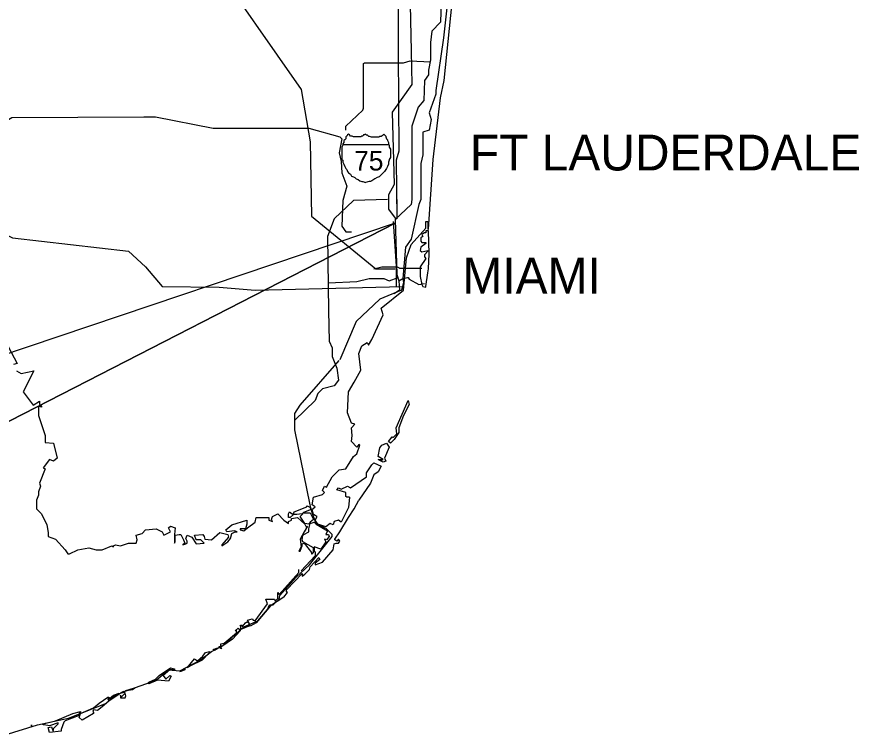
# Model space of a CAD drawing. Extents: x -820.2 to -798.1, y -2199.1 to -2182.2.
# Drawn here: x -805.629 to -804.571, y -2186.377 to -2185.475 of the extents above; entities that cross this region are included whole.
import ezdxf

# ---------------------------------------------------------------- set-up
doc = ezdxf.new("R2010")
doc.units = 0
for name, color, linetype in [('FLMap1', 7, 'Continuous'), ('FLMap2', 7, 'Continuous'), ('FLMap3', 7, 'Continuous'), ('TextMisc', 7, 'Continuous'), ('TextProjLabel', 7, 'Continuous')]:
    doc.layers.add(name, color=color, linetype=linetype)

msp = doc.modelspace()

# ---------------------------------------------------------------- linework, layer by layer
at = {"layer": 'FLMap1'}
msp.add_line((-805.2192, -2185.6357), (-805.1607, -2185.6357), dxfattribs=at)
for points in [[(-805.1904, -2185.6228), (-805.1919, -2185.6237), (-805.1929, -2185.6237), (-805.1939, -2185.6252), (-805.1954, -2185.6252), (-805.1964, -2185.6262), (-805.1979, -2185.6262), (-805.1989, -2185.6262), (-805.1999, -2185.6262), (-805.2013, -2185.6262), (-805.2038, -2185.6262), (-805.2048, -2185.6262), (-805.2058, -2185.6262), (-805.2073, -2185.6252), (-805.2093, -2185.6252), (-805.2108, -2185.6237), (-805.2118, -2185.6228), (-805.2132, -2185.6237), (-805.2142, -2185.6252), (-805.2152, -2185.6262), (-805.2152, -2185.6287), (-805.2167, -2185.6297), (-805.2177, -2185.6307), (-805.2177, -2185.6332), (-805.2192, -2185.6347), (-805.2192, -2185.6366), (-805.2202, -2185.6391), (-805.2202, -2185.6416), (-805.2202, -2185.6451), (-805.2202, -2185.6476), (-805.2202, -2185.65), (-805.2202, -2185.652), (-805.2202, -2185.6545), (-805.2192, -2185.6555), (-805.2192, -2185.658), (-805.2177, -2185.6605), (-805.2167, -2185.6634), (-805.2152, -2185.6659), (-805.2142, -2185.6669), (-805.2132, -2185.6694), (-805.2118, -2185.6714), (-805.2093, -2185.6729), (-805.2083, -2185.6753), (-805.2058, -2185.6763), (-805.2038, -2185.6773), (-805.2023, -2185.6788), (-805.1999, -2185.6798), (-805.1979, -2185.6813), (-805.1954, -2185.6823), (-805.1939, -2185.6823), (-805.1904, -2185.6833)], [(-805.1904, -2185.6228), (-805.1894, -2185.6237), (-805.1884, -2185.6237), (-805.187, -2185.6252), (-805.186, -2185.6252), (-805.1835, -2185.6262), (-805.1825, -2185.6262), (-805.181, -2185.6262), (-805.18, -2185.6262), (-805.179, -2185.6262), (-805.1775, -2185.6262), (-805.1745, -2185.6262), (-805.1736, -2185.6262), (-805.1726, -2185.6252), (-805.1711, -2185.6252), (-805.1686, -2185.6237), (-805.1676, -2185.6228), (-805.1666, -2185.6237), (-805.1651, -2185.6252), (-805.1651, -2185.6262), (-805.1641, -2185.6287), (-805.1631, -2185.6297), (-805.1631, -2185.6307), (-805.1617, -2185.6332), (-805.1617, -2185.6347), (-805.1607, -2185.6366), (-805.1607, -2185.6391), (-805.1592, -2185.6416), (-805.1592, -2185.6451), (-805.1592, -2185.6476), (-805.1592, -2185.65), (-805.1592, -2185.652), (-805.1607, -2185.6545), (-805.1607, -2185.6555), (-805.1617, -2185.658), (-805.1617, -2185.6605), (-805.1631, -2185.6634), (-805.1641, -2185.6659), (-805.1651, -2185.6669), (-805.1666, -2185.6694), (-805.1686, -2185.6714), (-805.1701, -2185.6729), (-805.1726, -2185.6753), (-805.1736, -2185.6763), (-805.176, -2185.6773), (-805.179, -2185.6788), (-805.18, -2185.6798), (-805.1825, -2185.6813), (-805.1845, -2185.6823), (-805.186, -2185.6823), (-805.1904, -2185.6833)]]:
    msp.add_lwpolyline(points, dxfattribs=at)
at = {"layer": 'FLMap2'}
for points in [[(-805.6126, -2185.2521), (-805.5635, -2185.2531), (-805.5625, -2185.2556), (-805.5625, -2185.2928), (-805.4831, -2185.2938), (-805.4554, -2185.3082), (-805.44, -2185.3246), (-805.4236, -2185.3236), (-805.4077, -2185.3325), (-805.3958, -2185.3345), (-805.3899, -2185.3454), (-805.3889, -2185.398), (-805.2713, -2185.5667), (-805.2599, -2185.6322), (-805.2584, -2185.7255)], [(-805.0917, -2185.5553), (-805.0818, -2185.4575), (-805.0709, -2185.3851), (-805.0709, -2185.2978)], [(-805.1497, -2185.3335), (-805.1497, -2185.5201), (-805.1488, -2185.6441), (-805.1522, -2185.6555), (-805.1512, -2185.7289)], [(-805.0803, -2185.3955), (-805.0857, -2185.4372), (-805.0927, -2185.5017), (-805.1021, -2185.5677), (-805.1021, -2185.5726), (-805.1105, -2185.596), (-805.1081, -2185.6044), (-805.1105, -2185.6178), (-805.1185, -2185.6203), (-805.1185, -2185.6486), (-805.121, -2185.6595), (-805.121, -2185.7046), (-805.1234, -2185.7111), (-805.1334, -2185.7547), (-805.1403, -2185.7646), (-805.1438, -2185.8038), (-805.1428, -2185.8093), (-805.1453, -2185.8187), (-805.1726, -2185.8301), (-805.2023, -2185.8579), (-805.2227, -2185.906)], [(-805.9029, -2185.4575), (-805.8994, -2185.533), (-805.8979, -2185.5984), (-805.8949, -2185.6143), (-805.881, -2185.6237), (-805.8607, -2185.6486), (-805.7947, -2185.6952), (-805.7888, -2185.6967), (-805.7808, -2185.7036), (-805.763, -2185.7101), (-805.7515, -2185.7111), (-805.7446, -2185.718), (-805.7188, -2185.7289), (-805.6994, -2185.7324), (-805.6816, -2185.7393), (-805.6672, -2185.7408), (-805.6603, -2185.7393), (-805.634, -2185.7527), (-805.4881, -2185.7696)], [(-805.115, -2185.7324), (-805.1125, -2185.7324), (-805.1125, -2185.7418), (-805.1115, -2185.7418), (-805.1056, -2185.6545), (-805.0962, -2185.5771), (-805.0917, -2185.5553)], [(-805.1512, -2185.7046), (-805.1512, -2185.7289)], [(-805.2584, -2185.7255), (-805.1775, -2185.7919), (-805.1532, -2185.7919)], [(-805.2073, -2186.0013), (-805.2083, -2185.9914), (-805.2038, -2185.9869), (-805.2083, -2185.9854), (-805.2132, -2185.9725), (-805.2118, -2185.9462), (-805.2048, -2185.9343), (-805.1964, -2185.9189), (-805.1989, -2185.8981), (-805.1954, -2185.8887), (-805.1884, -2185.8842), (-805.187, -2185.8877), (-805.1825, -2185.8807), (-805.1686, -2185.8495), (-805.1711, -2185.841), (-805.1428, -2185.8187), (-805.1393, -2185.778), (-805.1334, -2185.7612), (-805.115, -2185.7408), (-805.115, -2185.7324)], [(-805.1557, -2185.7324), (-805.1522, -2185.7885), (-805.1522, -2185.8093)], [(-805.115, -2185.8148), (-805.115, -2185.8138), (-805.1125, -2185.7969), (-805.1115, -2185.7919), (-805.1105, -2185.7731), (-805.1115, -2185.7443), (-805.114, -2185.7443), (-805.115, -2185.7443), (-805.115, -2185.7468), (-805.115, -2185.7468), (-805.1165, -2185.7468), (-805.1185, -2185.7478), (-805.12, -2185.7488), (-805.1185, -2185.7513), (-805.121, -2185.7527), (-805.121, -2185.7572), (-805.12, -2185.7587), (-805.115, -2185.7587), (-805.115, -2185.7602), (-805.121, -2185.7646), (-805.122, -2185.7686), (-805.12, -2185.7706), (-805.1125, -2185.7686), (-805.1125, -2185.7696), (-805.1165, -2185.7741), (-805.1165, -2185.7766), (-805.115, -2185.779), (-805.122, -2185.7895), (-805.122, -2185.8014), (-805.12, -2185.8113), (-805.1185, -2185.8138), (-805.115, -2185.8148)], [(-805.4881, -2185.7696), (-805.4668, -2185.7895), (-805.4459, -2185.8138), (-805.3745, -2185.8148), (-805.3293, -2185.8187), (-805.1438, -2185.8138)], [(-805.1522, -2185.8093), (-805.1522, -2185.8138)], [(-805.1428, -2185.8038), (-805.1378, -2185.8028), (-805.1368, -2185.8028), (-805.1359, -2185.8048), (-805.1234, -2185.8113), (-805.1165, -2185.8103)], [(-805.6479, -2185.8733), (-805.628, -2185.9105), (-805.6325, -2185.912)], [(-805.6444, -2186.3774), (-805.6027, -2186.3645), (-805.5635, -2186.356), (-805.5159, -2186.3372), (-805.506, -2186.3282), (-805.4926, -2186.3223), (-805.4534, -2186.3084), (-805.438, -2186.2955), (-805.4236, -2186.2965), (-805.3983, -2186.2831), (-805.3839, -2186.2722), (-805.37, -2186.2652), (-805.3432, -2186.2414), (-805.3259, -2186.234), (-805.3135, -2186.2196), (-805.311, -2186.2136), (-805.3065, -2186.2136), (-805.2991, -2186.2067), (-805.2981, -2186.2022), (-805.2777, -2186.1789), (-805.2609, -2186.1635), (-805.2326, -2186.1278), (-805.2326, -2186.1253), (-805.2395, -2186.1184), (-805.249, -2186.1134), (-805.2524, -2186.1114), (-805.2574, -2186.098), (-805.2599, -2186.0881), (-805.2792, -2185.9939), (-805.2792, -2185.9735), (-805.2728, -2185.9631), (-805.2237, -2185.907)], [(-805.629, -2185.9199), (-805.623, -2185.9234), (-805.6072, -2185.9199), (-805.6206, -2185.9462), (-805.6082, -2185.9631), (-805.6002, -2185.9581), (-805.6002, -2185.9621), (-805.5977, -2185.9641), (-805.5977, -2185.9656), (-805.6012, -2185.9641), (-805.6012, -2185.976), (-805.5928, -2186.0013), (-805.5928, -2186.0097), (-805.5824, -2186.0107), (-805.5779, -2186.0296), (-805.5824, -2186.0335), (-805.5873, -2186.0311), (-805.5953, -2186.0415)], [(-805.1592, -2186.0107), (-805.1617, -2186.0087), (-805.1572, -2186.0028), (-805.1557, -2186.0038), (-805.1512, -2185.9988), (-805.1522, -2185.9914), (-805.1368, -2185.9571), (-805.1359, -2185.9621), (-805.1428, -2185.976), (-805.1488, -2185.9914), (-805.1488, -2185.9973), (-805.1547, -2186.0063), (-805.1592, -2186.0107), (-805.1617, -2186.0087)], [(-805.2559, -2186.0787), (-805.2445, -2186.0752), (-805.242, -2186.0727), (-805.2445, -2186.0703), (-805.242, -2186.0648), (-805.2395, -2186.0658), (-805.2326, -2186.0529), (-805.2237, -2186.044), (-805.2152, -2186.043), (-805.2058, -2186.0276), (-805.2013, -2186.0241), (-805.1979, -2186.0132), (-805.1989, -2186.0122), (-805.2013, -2186.0157), (-805.2083, -2186.0087), (-805.2073, -2186.0013)], [(-805.1701, -2186.0321), (-805.1686, -2186.0311), (-805.1745, -2186.0276), (-805.1726, -2186.0167), (-805.1701, -2186.0132), (-805.1641, -2186.0107), (-805.1607, -2186.0157), (-805.1666, -2186.0296), (-805.1651, -2186.0335), (-805.1686, -2186.0345), (-805.1711, -2186.0335), (-805.1745, -2186.0311), (-805.1745, -2186.0311), (-805.1711, -2186.0311), (-805.1701, -2186.0321), (-805.1686, -2186.0311)], [(-805.5953, -2186.0415), (-805.5928, -2186.043), (-805.6002, -2186.0608), (-805.5987, -2186.0648), (-805.6012, -2186.0717), (-805.6012, -2186.0762), (-805.6037, -2186.0822), (-805.6037, -2186.0931), (-805.5977, -2186.0995), (-805.5908, -2186.1134), (-805.5893, -2186.1228), (-805.5893, -2186.1278), (-805.5799, -2186.1313), (-805.568, -2186.1447), (-805.5645, -2186.1496), (-805.5625, -2186.1496), (-805.5521, -2186.1447), (-805.5382, -2186.1422), (-805.5288, -2186.1447), (-805.5213, -2186.1447), (-805.5094, -2186.1397), (-805.507, -2186.1407), (-805.507, -2186.1397), (-805.5045, -2186.1382), (-805.4985, -2186.1397), (-805.4881, -2186.1362), (-805.4787, -2186.1362), (-805.4772, -2186.1323), (-805.4787, -2186.1263), (-805.4712, -2186.1243), (-805.4668, -2186.1194), (-805.4534, -2186.1184), (-805.4459, -2186.1219), (-805.4439, -2186.1263), (-805.4355, -2186.1219), (-805.438, -2186.1169), (-805.4355, -2186.1149), (-805.4296, -2186.1169), (-805.4305, -2186.1253), (-805.4305, -2186.1323), (-805.4305, -2186.1362), (-805.4296, -2186.1348), (-805.4296, -2186.1263), (-805.4246, -2186.1253)], [(-805.2108, -2186.0787), (-805.2142, -2186.0787), (-805.2152, -2186.0777), (-805.2152, -2186.0727), (-805.2266, -2186.0693), (-805.2247, -2186.0668), (-805.2212, -2186.0683), (-805.2132, -2186.0648), (-805.2093, -2186.0668), (-805.1894, -2186.0529), (-805.1894, -2186.0479), (-805.1825, -2186.038), (-805.18, -2186.0355), (-805.1711, -2186.0395), (-805.1745, -2186.0469), (-805.18, -2186.0504), (-805.1845, -2186.0608), (-805.1989, -2186.0822)], [(-805.2108, -2186.0787), (-805.2118, -2186.0916), (-805.2212, -2186.1099), (-805.2247, -2186.1075), (-805.2301, -2186.109), (-805.2311, -2186.1134), (-805.2351, -2186.1114), (-805.2405, -2186.1159), (-805.2505, -2186.1124), (-805.2539, -2186.1075), (-805.2514, -2186.103), (-805.2539, -2186.1015), (-805.2559, -2186.1005), (-805.2574, -2186.0946), (-805.2599, -2186.0946), (-805.2693, -2186.098), (-805.2599, -2186.098), (-805.2559, -2186.1065), (-805.2599, -2186.1099), (-805.2619, -2186.1124), (-805.2668, -2186.1114), (-805.2728, -2186.103), (-805.2693, -2186.0995), (-805.2703, -2186.0995), (-805.2768, -2186.1005), (-805.2792, -2186.1005), (-805.2812, -2186.1005), (-805.2852, -2186.104), (-805.2872, -2186.104), (-805.2872, -2186.0995), (-805.2862, -2186.097), (-805.2827, -2186.0995), (-805.2812, -2186.0995), (-805.2802, -2186.097), (-805.2643, -2186.0906), (-805.2643, -2186.0896), (-805.2609, -2186.0906), (-805.2584, -2186.0946), (-805.2539, -2186.0906), (-805.2574, -2186.0881), (-805.2559, -2186.0787)], [(-805.2668, -2186.1754), (-805.2609, -2186.1695), (-805.2599, -2186.166), (-805.249, -2186.1541), (-805.248, -2186.1566), (-805.2539, -2186.1615), (-805.2539, -2186.1635), (-805.2445, -2186.1601), (-805.2311, -2186.1447), (-805.2301, -2186.1372), (-805.2276, -2186.1362), (-805.2247, -2186.1362), (-805.2227, -2186.1338), (-805.2247, -2186.1313), (-805.2266, -2186.1338), (-805.2291, -2186.1323), (-805.2291, -2186.1313), (-805.2227, -2186.1219), (-805.2118, -2186.104), (-805.2048, -2186.0931), (-805.1989, -2186.0822)], [(-805.4246, -2186.1253), (-805.4226, -2186.1253), (-805.4191, -2186.1323), (-805.4177, -2186.1362), (-805.4201, -2186.1382), (-805.4162, -2186.1372), (-805.4147, -2186.1362), (-805.4147, -2186.1338), (-805.4162, -2186.1303), (-805.4147, -2186.1263), (-805.4087, -2186.1288), (-805.4033, -2186.1372), (-805.3933, -2186.1362), (-805.3973, -2186.1323), (-805.4033, -2186.1323), (-805.4052, -2186.1263), (-805.3948, -2186.1253), (-805.3933, -2186.1278), (-805.3923, -2186.1313), (-805.3839, -2186.1323), (-805.3735, -2186.1228), (-805.3636, -2186.1253), (-805.3626, -2186.1288), (-805.371, -2186.1382), (-805.371, -2186.1397), (-805.3636, -2186.1348), (-805.3601, -2186.1303), (-805.3586, -2186.1243), (-805.3541, -2186.1219), (-805.3517, -2186.1219), (-805.3551, -2186.1209), (-805.3646, -2186.1219), (-805.3661, -2186.1194), (-805.3586, -2186.1134), (-805.3398, -2186.1075), (-805.3398, -2186.1124), (-805.3412, -2186.1184), (-805.3482, -2186.1184), (-805.3482, -2186.1194), (-805.3432, -2186.1209), (-805.3388, -2186.1169), (-805.3293, -2186.1099), (-805.3279, -2186.104), (-805.3145, -2186.104), (-805.312, -2186.104), (-805.312, -2186.1075), (-805.3075, -2186.109)], [(-805.3075, -2186.109), (-805.3085, -2186.1065), (-805.3075, -2186.103), (-805.3006, -2186.0995), (-805.2931, -2186.1075), (-805.2872, -2186.1114), (-805.2872, -2186.109), (-805.2837, -2186.1075), (-805.2837, -2186.1055), (-805.2758, -2186.104), (-805.2668, -2186.1124), (-805.2653, -2186.1159), (-805.2634, -2186.1149), (-805.2678, -2186.1219), (-805.2728, -2186.1313), (-805.2713, -2186.1407), (-805.2743, -2186.1462), (-805.2728, -2186.1462), (-805.2703, -2186.1397), (-805.2703, -2186.1372), (-805.2678, -2186.1362), (-805.2584, -2186.1482), (-805.2584, -2186.1496), (-805.2574, -2186.1496), (-805.2559, -2186.1482), (-805.2559, -2186.1422), (-805.2693, -2186.1348), (-805.2703, -2186.1323), (-805.2693, -2186.1263), (-805.2634, -2186.1228), (-805.2619, -2186.1219), (-805.2619, -2186.1184), (-805.2599, -2186.1114), (-805.2549, -2186.1099), (-805.2524, -2186.1124), (-805.2385, -2186.1209), (-805.2405, -2186.1253), (-805.2405, -2186.1253), (-805.2371, -2186.1253), (-805.2361, -2186.1278), (-805.2395, -2186.1323), (-805.242, -2186.1313), (-805.2405, -2186.1348), (-805.2465, -2186.1437), (-805.2549, -2186.1407), (-805.2549, -2186.1462), (-805.2539, -2186.1472), (-805.2539, -2186.1521), (-805.2713, -2186.171)], [(-805.3006, -2186.2057), (-805.3006, -2186.1983), (-805.2991, -2186.2007), (-805.2743, -2186.173), (-805.2743, -2186.1695)], [(-805.2931, -2186.2042), (-805.2887, -2186.1983), (-805.2897, -2186.1973), (-805.2897, -2186.1948), (-805.2703, -2186.1744), (-805.2703, -2186.1769), (-805.2703, -2186.1779), (-805.2668, -2186.1754)], [(-805.2931, -2186.2042), (-805.31, -2186.2151), (-805.3279, -2186.2365), (-805.3353, -2186.2404), (-805.3363, -2186.2394), (-805.3363, -2186.2375), (-805.3388, -2186.233)], [(-805.3363, -2186.2375), (-805.3388, -2186.233), (-805.3328, -2186.2315), (-805.3318, -2186.233), (-805.3293, -2186.234), (-805.3135, -2186.2126), (-805.3159, -2186.2067), (-805.305, -2186.2067), (-805.304, -2186.2092), (-805.3006, -2186.2057)], [(-805.3482, -2186.2439), (-805.3472, -2186.2439), (-805.3472, -2186.2414), (-805.3482, -2186.2404), (-805.3472, -2186.2394), (-805.3457, -2186.2394), (-805.3457, -2186.2414), (-805.3412, -2186.2365), (-805.3412, -2186.2365), (-805.3398, -2186.235), (-805.3373, -2186.2365), (-805.3373, -2186.2404)], [(-805.371, -2186.2662), (-805.3725, -2186.2652), (-805.3725, -2186.2628), (-805.3725, -2186.2628), (-805.368, -2186.2618), (-805.3527, -2186.2489), (-805.3527, -2186.2449), (-805.3541, -2186.2464), (-805.3507, -2186.2429), (-805.3492, -2186.2449), (-805.3482, -2186.2449), (-805.3482, -2186.2464), (-805.3576, -2186.2568)], [(-805.3373, -2186.2404), (-805.3472, -2186.2449), (-805.3482, -2186.2439)], [(-805.3745, -2186.2662), (-805.3725, -2186.2662), (-805.3725, -2186.2662), (-805.3725, -2186.2677), (-805.371, -2186.2687), (-805.3725, -2186.2687), (-805.3735, -2186.2677), (-805.3745, -2186.2677), (-805.3745, -2186.2662)], [(-805.3576, -2186.2568), (-805.371, -2186.2662)], [(-805.4147, -2186.293), (-805.4052, -2186.2816), (-805.4018, -2186.2841), (-805.3948, -2186.2781), (-805.3914, -2186.2737), (-805.3864, -2186.2722), (-805.3864, -2186.2737), (-805.3958, -2186.2831), (-805.4102, -2186.2905), (-805.4147, -2186.293)], [(-805.3819, -2186.2697), (-805.376, -2186.2677), (-805.376, -2186.2687)], [(-805.376, -2186.2687), (-805.3804, -2186.2712), (-805.3819, -2186.2697)], [(-805.4628, -2186.3109), (-805.4544, -2186.3069), (-805.4499, -2186.3024), (-805.4355, -2186.293), (-805.4305, -2186.294), (-805.4305, -2186.2955), (-805.4365, -2186.2955), (-805.4449, -2186.3024), (-805.4415, -2186.3069), (-805.4365, -2186.3024), (-805.4345, -2186.3034), (-805.438, -2186.3094), (-805.4519, -2186.3084), (-805.4628, -2186.3129), (-805.4638, -2186.3119)], [(-805.4236, -2186.2975), (-805.4177, -2186.294), (-805.4177, -2186.2955)], [(-805.4177, -2186.2955), (-805.4226, -2186.2975), (-805.4236, -2186.2975), (-805.4236, -2186.2975)], [(-805.4916, -2186.3213), (-805.4807, -2186.3178), (-805.4807, -2186.3188), (-805.4831, -2186.3203), (-805.4881, -2186.3213), (-805.4916, -2186.3223)], [(-805.4638, -2186.3119), (-805.4628, -2186.3109)], [(-805.5, -2186.3248), (-805.5, -2186.3258), (-805.5129, -2186.3347), (-805.5213, -2186.3416), (-805.5273, -2186.3466), (-805.5323, -2186.3456), (-805.5332, -2186.3476), (-805.5323, -2186.3491), (-805.5323, -2186.3501), (-805.5466, -2186.3585), (-805.5501, -2186.355), (-805.5486, -2186.3501)], [(-805.5486, -2186.3501), (-805.5323, -2186.3431), (-805.5253, -2186.3372), (-805.5144, -2186.3297), (-805.5129, -2186.3297), (-805.5144, -2186.3332), (-805.507, -2186.3273), (-805.5, -2186.3248)], [(-805.4985, -2186.3307), (-805.4926, -2186.3307), (-805.4916, -2186.3282), (-805.4926, -2186.3248), (-805.4975, -2186.3297), (-805.4985, -2186.3273)], [(-805.4985, -2186.3273), (-805.4985, -2186.3297), (-805.4985, -2186.3307)], [(-805.4985, -2186.3273), (-805.4985, -2186.3273)], [(-805.4975, -2186.3238), (-805.4941, -2186.3223), (-805.4926, -2186.3238)], [(-805.4926, -2186.3238), (-805.4975, -2186.3248), (-805.4975, -2186.3238)], [(-805.4916, -2186.3223), (-805.4916, -2186.3213)], [(-805.5953, -2186.363), (-805.5799, -2186.3595), (-805.5581, -2186.3501), (-805.5486, -2186.3476), (-805.5486, -2186.3491), (-805.5501, -2186.3501), (-805.5501, -2186.3526), (-805.568, -2186.3595), (-805.5695, -2186.361), (-805.5729, -2186.3704), (-805.5729, -2186.3724), (-805.5873, -2186.3739), (-805.5893, -2186.3679), (-805.5848, -2186.3669), (-805.5834, -2186.3714), (-805.5824, -2186.3714), (-805.5824, -2186.3689), (-805.5764, -2186.363), (-805.5764, -2186.362), (-805.5873, -2186.3655), (-805.5943, -2186.3645), (-805.5953, -2186.3645)], [(-805.6101, -2186.3655), (-805.6101, -2186.3645)], [(-805.6101, -2186.3645), (-805.6101, -2186.3669), (-805.6101, -2186.3669), (-805.6101, -2186.3655)], [(-805.5953, -2186.3645), (-805.5953, -2186.363)]]:
    msp.add_lwpolyline(points, dxfattribs=at)
at = {"layer": 'FLMap3'}
for points in [[(-805.4692, -2184.817), (-805.4355, -2184.8662), (-805.4236, -2184.8696), (-805.3646, -2184.8711), (-805.3412, -2184.891), (-805.3259, -2184.9103), (-805.2768, -2184.9118), (-805.2599, -2184.9341), (-805.2371, -2184.9798), (-805.2361, -2185.0095), (-805.2152, -2185.0597), (-805.179, -2185.1147), (-805.1651, -2185.1495), (-805.1324, -2185.1877), (-805.115, -2185.2278), (-805.1185, -2185.3117), (-805.1368, -2185.3429), (-805.1334, -2185.5186)], [(-805.0952, -2185.4432), (-805.0962, -2185.4819), (-805.1071, -2185.4933), (-805.1091, -2185.5077)], [(-805.1091, -2185.5077), (-805.1091, -2185.5295), (-805.1115, -2185.5424), (-805.1115, -2185.5483), (-805.1165, -2185.5553), (-805.1175, -2185.5806), (-805.1244, -2185.589), (-805.1324, -2185.6128), (-805.1324, -2185.6545), (-805.1324, -2185.6753), (-805.1324, -2185.7046), (-805.1334, -2185.7111), (-805.1532, -2185.7299), (-805.1512, -2185.7989), (-805.1488, -2185.8068), (-805.1438, -2185.8038)], [(-805.1334, -2185.5186), (-805.1324, -2185.5602), (-805.1572, -2185.595), (-805.1547, -2185.6858), (-805.1617, -2185.6987), (-805.1617, -2185.717), (-805.1522, -2185.7299)], [(-805.1929, -2185.589), (-805.1929, -2185.5339), (-805.1919, -2185.533), (-805.1428, -2185.533), (-805.1344, -2185.5305), (-805.1091, -2185.532)], [(-805.2152, -2185.6178), (-805.2152, -2185.6153), (-805.2152, -2185.6128), (-805.1939, -2185.5925), (-805.1929, -2185.59), (-805.1929, -2185.589)], [(-805.8354, -2185.6079), (-805.6454, -2185.6079), (-805.635, -2185.6019), (-805.4692, -2185.6009), (-805.4544, -2185.6009), (-805.3819, -2185.6153), (-805.2619, -2185.6153)], [(-805.2619, -2185.6153), (-805.2227, -2185.6262), (-805.2202, -2185.6287), (-805.2237, -2185.6461), (-805.2212, -2185.657), (-805.2202, -2185.6714), (-805.2142, -2185.6882), (-805.2192, -2185.7061), (-805.2202, -2185.7384), (-805.2152, -2185.7453), (-805.2083, -2185.7453)], [(-805.1631, -2185.7046), (-805.2058, -2185.7061), (-805.2301, -2185.7289), (-805.2385, -2185.7513), (-805.2371, -2185.8445), (-805.2361, -2185.8827), (-805.2326, -2185.8912), (-805.2326, -2185.9021), (-805.2266, -2185.9165), (-805.2247, -2185.9318), (-805.2301, -2185.9388), (-805.2445, -2185.9423), (-805.2505, -2185.9482), (-805.2539, -2185.9571), (-805.2792, -2185.9819)], [(-805.18, -2185.7919), (-805.1701, -2185.7895), (-805.1641, -2185.7895), (-805.1512, -2185.7895)], [(-805.1478, -2185.7909), (-805.1512, -2185.7895)], [(-805.1478, -2185.7909), (-805.12, -2185.7909)], [(-805.2371, -2185.8093), (-805.2013, -2185.8078), (-805.186, -2185.8038), (-805.1676, -2185.8038), (-805.1607, -2185.8068), (-805.1497, -2185.8028)], [(-805.1488, -2185.8068), (-805.1478, -2185.8187), (-805.1547, -2185.8232)]]:
    msp.add_lwpolyline(points, dxfattribs=at)
at = {"layer": 'TextProjLabel'}
for p, q in [((-805.1532, -2185.7344), (-806.3633, -2186.3545)), ((-805.1532, -2185.7344), (-805.9582, -2186.0055)), ((-805.8473, -2186.0902), (-805.1532, -2185.7344))]:
    msp.add_line(p, q, dxfattribs=at)

# ---------------------------------------------------------------- texts
at = {"layer": 'TextMisc'}
for s, height, p in [('FT LAUDERDALE', 0.045, (-805.0595, -2185.6683)), ('75', 0.0247, (-805.2048, -2185.6684)), ('MIAMI', 0.045, (-805.0689, -2185.823))]:
    msp.add_text(s, height=height, dxfattribs=at).set_placement(p)

doc.saveas('drawing.dxf')
